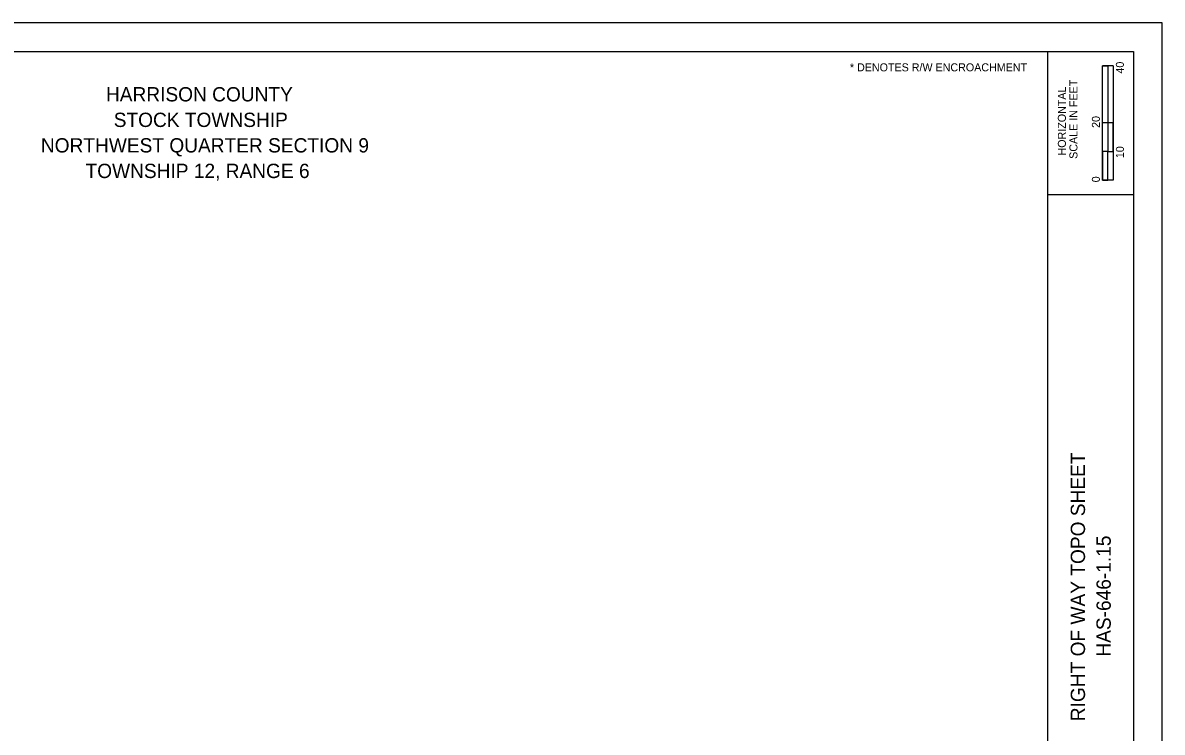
# Model space of a CAD drawing. Extents: x -0.4 to 34, y 0 to 22.
# Drawn here: x 14.07 to 34, y 9.59 to 22 of the extents above; entities that cross this region are included whole.
import ezdxf

# ---------------------------------------------------------------- set-up
doc = ezdxf.new("R2010")
doc.units = 0
for name, color, linetype in [('Default', 7, 'Continuous'), ('SH_Border', 7, 'Continuous'), ('SH_Cut_Line', 7, 'Continuous'), ('SH_Data', 7, 'Continuous')]:
    doc.layers.add(name, color=color, linetype=linetype)

msp = doc.modelspace()

# ---------------------------------------------------------------- linework, layer by layer
at = {"layer": 'SH_Border'}
for p, q in [((32, 0.5), (32, 21.5)), ((32, 19), (33.5, 19))]:
    msp.add_line(p, q, dxfattribs=at)
msp.add_lwpolyline([(1.5, 21.5), (33.5, 21.5), (33.5, 0.5), (1.5, 0.5)], close=True, dxfattribs=at)
at = {"layer": 'SH_Cut_Line'}
msp.add_lwpolyline([(0, 0), (34, 0), (34, 22), (0, 22)], close=True, dxfattribs=at)
at = {"layer": 'SH_Data'}
for p, q in [((32.957, 19.25), (32.957, 21.25)), ((33.144, 21.25), (32.957, 21.25)), ((32.957, 20.25), (32.957, 21.25)), ((32.957, 21.25), (33.05, 21.25)), ((33.05, 21.25), (33.051, 21.25)), ((33.051, 21.25), (33.051, 20.25)), ((33.144, 21.25), (33.144, 19.25)), ((33.051, 20.25), (32.957, 20.25)), ((33.143, 20.25), (33.05, 20.25)), ((33.05, 20.25), (33.05, 19.75)), ((33.143, 19.75), (33.143, 20.25)), ((33.05, 19.75), (32.957, 19.75)), ((32.957, 19.75), (32.957, 19.25)), ((33.05, 19.25), (33.05, 19.75)), ((33.05, 19.75), (33.143, 19.75)), ((33.144, 19.25), (32.957, 19.25)), ((32.957, 19.25), (33.05, 19.25))]:
    msp.add_line(p, q, dxfattribs=at)

# ---------------------------------------------------------------- texts
at = {"layer": 'Default'}
msp.add_text('* DENOTES R/W ENCROACHMENT', height=0.14, dxfattribs=at).set_placement((28.537, 21.151))
at = {"layer": 'SH_Data'}
for s, height, p in [('40', 0.14, (33.33, 21.112)), ('SCALE IN FEET', 0.14, (32.517, 19.621)), ('HORIZONTAL', 0.14, (32.315, 19.679)), ('20', 0.14, (32.91, 20.162)), ('10', 0.14, (33.33, 19.633)), ('0', 0.14, (32.91, 19.211)), ('RIGHT OF WAY TOPO SHEET', 0.25, (32.65, 9.787)), ('HAS-646-1.15', 0.25, (33.1, 10.915))]:
    msp.add_text(s, height=height, rotation=90, dxfattribs=at).set_placement(p)
for s, p in [('HARRISON COUNTY', (15.523, 20.625)), ('STOCK TOWNSHIP', (15.659, 20.178)), ('NORTHWEST QUARTER SECTION 9', (14.385, 19.732)), ('TOWNSHIP 12, RANGE 6', (15.166, 19.285))]:
    msp.add_text(s, height=0.25, dxfattribs=at).set_placement(p)

doc.saveas('drawing.dxf')
